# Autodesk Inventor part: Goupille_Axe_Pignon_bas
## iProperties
Created: 2008-11
Part Number: Goupille_Axe_Pignon_bas
Document SubType Name: Modeling
Designer: ETUDIANT
Author: ETUDIANT
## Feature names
1. Balayage1
